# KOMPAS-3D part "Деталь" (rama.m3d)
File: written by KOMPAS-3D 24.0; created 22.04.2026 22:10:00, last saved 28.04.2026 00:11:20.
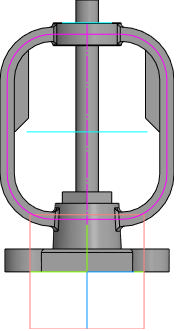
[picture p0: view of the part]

Document properties: Автор: mrdid; Полное имя файла: C:\Работа\ГОТОВЫЕ ИСХОДНИКИ\VSO2130M-F-S Клапан запорный сальниковый DN.ru Ду15-100 Ру40\исходные материалы\DN25\rama.m3d

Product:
- Part/product: Деталь
    Масса: 0.732425

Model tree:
1. Эскиз:2  (with: Ребро.Элемент выдавливания:14)
2. Элемент выдавливания:1
     Расстояние 1 = 10
3. Эскиз:3  (with: Грань.Элемент выдавливания:1, Ребро.Элемент выдавливания:1)
4. Элемент выдавливания:2
     Расстояние 2 = 10
5. Эскиз:4  (with: Грань.Элемент выдавливания:1)
6. Элемент выдавливания:3
     Угол 1 = -3
7. Эскиз:5  (with: Грань.Элемент выдавливания:3, Ребро.Элемент выдавливания:3)
8. Элемент выдавливания:4
9. Эскиз:23  (with: Грань.Элемент выдавливания:4, Ребро.Элемент выдавливания:4)
10. Элемент выдавливания:21  (labels: Деталь2; Грань.Твердое тело1)
     Расстояние 1 = 83.9875
11. Эскиз:7  (with: Грань.Элемент выдавливания:4, Ребро.Элемент выдавливания:3)
12. Элемент выдавливания:6  (with: Грань.Элемент выдавливания:3)
     Расстояние 2 = 5
13. Смещенная плоскость:4  (labels: Деталь2; Грань.Твердое тело1)
     Расстояние = 10
14. Эскиз:24  (with: Ребро.Элемент выдавливания:3)
15. Элемент выдавливания:22
     Расстояние 2 = 10
16. Эскиз:25  (with: Ребро.Элемент выдавливания:3)
17. Эскиз:26  (with: Ребро.Элемент выдавливания:3)
18. Элемент по траектории:1
     Длина траектории = 267.639
19. Скругление:8  (with: Ребро.Элемент по траектории:1)
     Радиус = 2
20. Скругление:9  (with: Ребро.Элемент по траектории:1)
     Радиус = 1.5
21. Смещенная плоскость:5  (with: Грань.Элемент выдавливания:1)
22. Эскиз:27  (with: Вершина.Элемент по траектории:1)
23. Элемент выдавливания:23  (with: Грань.Элемент выдавливания:22)
     Расстояние 1 = 36.7375; Смещение 1 = -1
24. Скругление:1  (with: Ребро.Элемент выдавливания:1)
     Радиус = 1.5
25. Скругление:10  (with: Ребро.Элемент выдавливания:22)
     Радиус = 0.3
26. Фаска:1  (with: Ребро.Элемент выдавливания:23)
     Угол = 45; Длина 1 = 6; Длина 2 = 6
27. Массив по концентрической сетке:1  (with: Элемент выдавливания:2, Эскиз:3)  (labels: Клапан запорный DN.ru Ду25 Ру40)  (4 pattern instances)
     Шаг 2 = 360

Expressions: DN/2; DN/4; H/4
Referenced files in C:\Работа\ГОТОВЫЕ ИСХОДНИКИ\VSO2130M-F-S Клапан запорный сальниковый DN.ru Ду15-100 Ру40\исходные материалы\DN25\: VSO2130M-F-S Клапан запорный DN.ru Ду25 Ру40.a3d
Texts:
  DN+5
  Ось Y.Начало координат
